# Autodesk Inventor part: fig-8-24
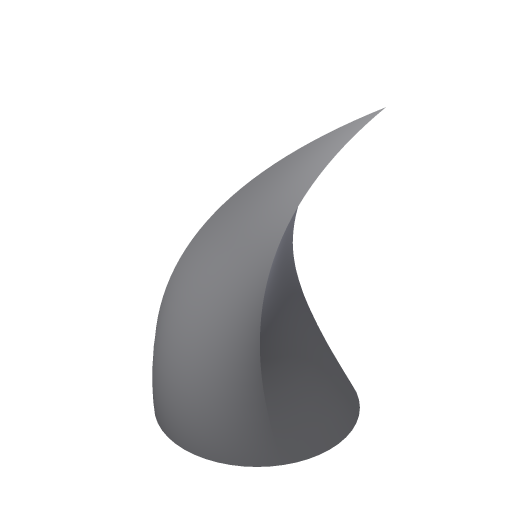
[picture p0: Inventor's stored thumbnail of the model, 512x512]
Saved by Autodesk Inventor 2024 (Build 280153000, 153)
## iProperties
Shininess: 77.0
Angle Display Precision: 2
Document Length Units: 11269
Document Angle Units: 11279
Document Time Units: 11290
Document Mass Units: 11283
Document Length Units Precision: 3
Document Angle Units Precision: 2
Created: 2001-12
Part Number: fig-8-24
Document SubType Name: Modeling
Designer: CADSoft
Density: 1 g/cm^3
Material: Generic
Appearance: Default
Density: 0.0
Volumn: 0.0
Area: 0.0
PropertySet Name: Model Information
Control State: 0
Master: False
Checked Out: False
Author: CADSoft
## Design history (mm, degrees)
workplane "Work Plane3"
workplane "Work Plane4"
sketch "Sketch12"
  geometry: L1 (0, 10.598)-(9.178, -5.299); L2 (9.178, -5.299)-(-9.178, -5.299); L3 (-9.178, -5.299)-(0, 10.598); 1 further point
  constraints: 6 end point, 5 other
workplane "Work Plane5"
loft "Loft5" dims "d57" = 0, "d58" = 90 deg, "d59" = 0, "d60" = 90 deg, "d61" = 0, "d62" = 90 deg
body "Solid1"
sketch "Sketch1"
  geometry: C1 r 19.387 at (0, 0); 1 further point
  constraints: 1 centre point, 1 coincident, 1 other
sketch "Sketch2"
  geometry: 1 further point
